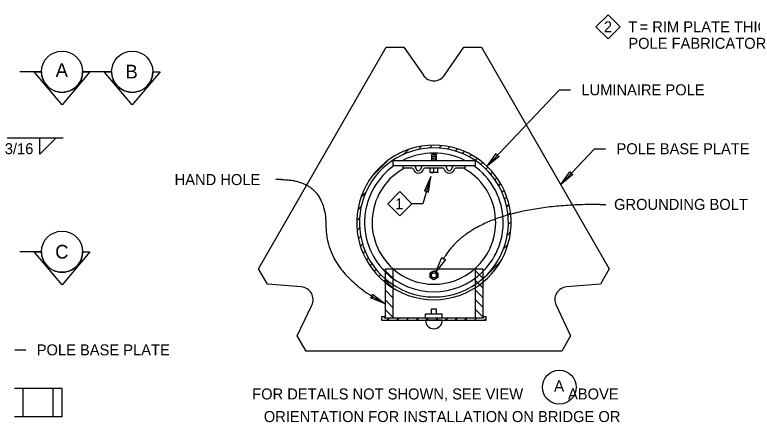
# Model space of a CAD drawing. Extents: x 99862 to 103151, y 100000 to 102076.
# Drawn here: x 100454 to 101528, y 100863 to 101456 of the extents above; entities that cross this region are included whole.
import ezdxf

# ---------------------------------------------------------------- set-up
doc = ezdxf.new("R2010")
doc.units = 0
for name, color, linetype in [('Level 15', 7, 'Continuous'), ('Level 20', 7, 'Continuous'), ('Level 21', 7, 'Continuous'), ('Level 3', 7, 'Continuous'), ('Level 62', 7, 'Continuous'), ('Level 7', 7, 'Continuous'), ('Level 8', 7, 'Continuous'), ('Level 9', 7, 'Continuous')]:
    doc.layers.add(name, color=color, linetype=linetype)

msp = doc.modelspace()

# ---------------------------------------------------------------- linework, layer by layer
at = {"layer": 'Level 15'}
for p, q in [((101247.4, 101347), (101142, 101235.6)), ((101247.4, 101347), (101263.4, 101347)), ((100425.2, 101277.3), (100524.4, 101277.3)), ((100490.5, 101253.3), (100490.5, 101277.3)), ((100490.5, 101253.3), (100514.5, 101277.3)), ((101298.6, 101261.2), (101249.3, 101209.2)), ((101298.6, 101261.2), (101314.6, 101261.2)), ((100842.1, 101216.3), (100834.1, 101216.3)), ((101060, 101220.9), (101048.6, 101181.2)), ((101048.6, 101181.2), (101032.6, 101181.2)), ((101307, 101180.2), (101315, 101180.2)), ((100454, 100968.4), (100470, 100968.4))]:
    msp.add_line(p, q, dxfattribs=at)
for points in [[(101142, 101235.6), (101155.5, 101254.2), (101156.9, 101251.4), (101159.8, 101250.1)], [(101249.3, 101209.2), (101262.8, 101227.8), (101264.3, 101225), (101267.2, 101223.7)], [(101060, 101220.9), (101050.8, 101199.8), (101054, 101200), (101056.6, 101198.2)], [(101067.4, 101081.8), (101076.3, 101103.1), (101078.3, 101100.7), (101081.4, 101100.1)], [(100993.4, 101035.4), (100972.1, 101044.3), (100974.5, 101046.3), (100975.1, 101049.4)]]:
    msp.add_lwpolyline(points, close=True, dxfattribs=at)
msp.add_open_spline([(101307, 101180.2), (101124.2, 101180.2), (101078.3, 101100.7)], degree=2, dxfattribs=at)
at = {"layer": 'Level 20'}
for points in [[(101318.2, 101456.3), (101335.8, 101438.7), (101318.2, 101421.2), (101300.7, 101438.7)], [(101015, 101198.8), (101032.6, 101181.2), (101015, 101163.7), (100997.4, 101181.2)]]:
    msp.add_lwpolyline(points, close=True, dxfattribs=at)
msp.add_open_spline([(100842.1, 101216.3), (100907.1, 101216.3), (100907.5, 101081.2), (100993.4, 101035.4)], degree=2, dxfattribs=at)
at = {"layer": 'Level 21'}
for p, q in [((101004.6, 101244.3), (101004.6, 101244.3)), ((101124.6, 101244.3), (101124.6, 101244.3)), ((100993.4, 101086.4), (100993.4, 101086.4))]:
    msp.add_line(p, q, dxfattribs=at)
at = {"layer": 'Level 3'}
for p, q in [((101041.5, 101259.8), (101046.7, 101265)), ((101058, 101262.1), (101062.2, 101266.3)), ((101072.1, 101262.1), (101075.8, 101265.8)), ((101020.5, 101252.9), (101027.8, 101260.2)), ((101084.6, 101260.4), (101088, 101263.9)), ((101096, 101257.7), (101099.2, 101260.9)), ((101106.4, 101254), (101109.4, 101257)), ((100974.2, 101220.8), (100997.6, 101244.2)), ((101116, 101249.4), (101118.9, 101252.4)), ((101124.8, 101244.1), (101127.7, 101247)), ((101132.9, 101238.1), (101135.8, 101241)), ((101140.4, 101231.4), (101143.3, 101234.3)), ((101147.2, 101224.1), (101150.1, 101227)), ((101153.4, 101216.1), (101156.3, 101219)), ((101158.9, 101207.4), (101161.8, 101210.4)), ((101163.6, 101198), (101166.7, 101201.1)), ((100958.4, 101190.8), (100965.6, 101198)), ((101167.6, 101187.9), (101170.7, 101191)), ((101170.6, 101176.7), (101173.9, 101180.1)), ((100953.6, 101171.9), (100958.7, 101177)), ((101172.5, 101164.5), (101176.2, 101168.2)), ((100952.2, 101156.4), (100956.4, 101160.6)), ((100952.7, 101142.7), (100956.5, 101146.4)), ((101173, 101150.9), (101177, 101154.9)), ((101171.3, 101135.1), (101176.2, 101140)), ((100954.7, 101130.5), (100958.1, 101133.9)), ((100957.7, 101119.4), (100960.9, 101122.6)), ((101166, 101115.6), (101172.5, 101122)), ((100961.5, 101109.1), (100964.6, 101112.2)), ((100966.2, 101099.6), (100969.1, 101102.6)), ((100971.5, 101090.8), (100974.4, 101093.7)), ((101135.9, 101071.3), (101161.6, 101097)), ((100977.6, 101082.7), (100980.4, 101085.5)), ((100993.4, 101086.4), (100993.4, 101015.2)), ((100993.4, 101086.4), (101004.6, 101086.4)), ((100993.4, 101083.9), (101004.6, 101072.6)), ((101004.6, 101086.4), (101004.6, 101015.2)), ((101004.6, 101086.4), (101124.6, 101086.4)), ((101124.6, 101086.4), (101124.6, 101015.2)), ((101124.6, 101086.4), (101135.9, 101086.4)), ((101124.6, 101084.1), (101135.9, 101072.9)), ((101135.9, 101086.4), (101135.9, 101015.2)), ((100984.2, 101075.2), (100987.1, 101078.1)), ((100991.5, 101068.4), (100993.4, 101070.2)), ((100993.4, 101069.7), (101004.6, 101058.5)), ((101124.6, 101070), (101135.9, 101058.7)), ((100993.4, 101055.6), (101004.6, 101044.3)), ((101124.6, 101055.8), (101135.9, 101044.6)), ((100993.4, 101041.4), (101004.6, 101030.2)), ((101124.6, 101041.7), (101135.9, 101030.4)), ((100988.7, 101011.4), (100988.7, 101017)), ((100988.7, 101017), (100992.4, 101017)), ((100992.4, 101015.2), (100992.4, 101017)), ((100993.4, 101027.3), (101004.6, 101016)), ((101124.6, 101027.6), (101135.9, 101016.3)), ((101136.8, 101015.2), (101136.8, 101017)), ((101136.8, 101017), (101140.6, 101017)), ((101140.6, 101017), (101140.6, 101017)), ((101140.6, 101011.4), (101140.6, 101017)), ((100988.7, 101011.4), (101140.6, 101011.4)), ((100992.4, 101015.2), (101136.8, 101015.2)), ((100996.2, 101011.4), (100999.9, 101015.2)), ((101004.6, 101015.2), (101124.6, 101015.2)), ((101010.3, 101011.4), (101014.1, 101015.2)), ((101024.5, 101011.4), (101028.2, 101015.2)), ((101038.6, 101011.4), (101042.4, 101015.2)), ((101052.8, 101011.4), (101056.5, 101015.2)), ((101066.9, 101011.4), (101070.7, 101015.2)), ((101081, 101011.4), (101084.8, 101015.2)), ((101095.2, 101011.4), (101098.9, 101015.2)), ((101109.3, 101011.4), (101113.1, 101015.2)), ((101123.5, 101011.4), (101127.2, 101015.2)), ((101137.6, 101011.4), (101140.6, 101014.4)), ((101140.6, 101011.4), (101140.6, 101011.4))]:
    msp.add_line(p, q, dxfattribs=at)
for radius, start, end in [(112.5, 309.2965, 230.7035), (108.5, 311.0634, 228.9366), (101, 63.5017, 116.4983), (101, 124.8487, 225.1147), (101, 314.8853, 55.1513), (101, 225.1147, 314.8853), (108.5, 228.9366, 311.0634), (112.5, 230.7035, 309.2965)]:
    msp.add_arc((101064.6, 101153.9), radius, start, end, dxfattribs=at)
at = {"layer": 'Level 62'}
for points in [[(101068.4, 101252.6), (101068.3, 101252.5), (101068.3, 101252.5), (101068.1, 101252.5), (101067, 101252.3), (101063.8, 101252.2), (101061.7, 101252.1), (101061.1, 101252), (101060.8, 101252), (101060.9, 101251.9)], [(101068.4, 101250.1), (101068.4, 101250), (101068.3, 101250), (101068.2, 101250), (101067.1, 101249.9), (101064, 101249.7), (101061.8, 101249.6), (101061.1, 101249.5), (101060.8, 101249.5), (101060.9, 101249.4)], [(101068.4, 101247.6), (101068.4, 101247.5), (101068.3, 101247.5), (101068.2, 101247.5), (101067.3, 101247.4), (101064.2, 101247.2), (101061.9, 101247.1), (101061.2, 101247), (101060.8, 101247), (101060.9, 101246.9)], [(101068.4, 101245.1), (101068.4, 101245), (101068.3, 101245), (101068.2, 101245), (101067.4, 101244.9), (101064.3, 101244.7), (101062, 101244.6), (101061.2, 101244.5), (101060.8, 101244.5), (101060.9, 101244.4)]]:
    msp.add_open_spline(points, degree=4, dxfattribs=at)
at = {"layer": 'Level 7'}
for p, q in [((100809.1, 101086.5), (100995.2, 101408.9)), ((100995.2, 101408.9), (101021, 101408.9)), ((101021, 101408.9), (101049.2, 101368.2)), ((101080, 101368.2), (101108.3, 101408.9)), ((101108.3, 101408.9), (101134, 101408.9)), ((101134, 101408.9), (101320.1, 101086.5)), ((100822, 101064.2), (100809.1, 101086.5)), ((101320.1, 101086.5), (101307.3, 101064.2)), ((100871.3, 101060.1), (100822, 101064.2)), ((101307.3, 101064.2), (101257.9, 101060.1)), ((100865.6, 100988.6), (100886.7, 101033.4)), ((101242.5, 101033.4), (101263.6, 100988.6)), ((100878.5, 100966.3), (100865.6, 100988.6)), ((101263.6, 100988.6), (101250.8, 100966.3)), ((101250.8, 100966.3), (100878.5, 100966.3))]:
    msp.add_line(p, q, dxfattribs=at)
for centre, radius, start, end in [((101064.6, 101378.9), 18.8, 214.7607, 325.2393), ((101064.6, 101153.9), 90, 118.4802, 228.5904), ((101064.6, 101153.9), 90, 311.4096, 61.5198), ((101064.6, 101153.9), 90, 228.5904, 311.4096), ((100869.8, 101041.4), 18.8, 334.7607, 85.2393), ((101259.5, 101041.4), 18.8, 94.7607, 205.2393)]:
    msp.add_arc(centre, radius, start, end, dxfattribs=at)
at = {"layer": 'Level 8'}
for p, q in [((101004.6, 101244.3), (101124.6, 101244.3)), ((101004.6, 101244.3), (101004.6, 101236.8)), ((101124.6, 101244.3), (101124.6, 101236.8)), ((101004.6, 101236.8), (101019.6, 101236.8)), ((101019.6, 101236.8), (101109.6, 101236.8)), ((101019.6, 101233), (101019.6, 101236.8)), ((101019.6, 101236.8), (101034.6, 101236.8)), ((101032.9, 101233), (101019.6, 101233)), ((101077.9, 101233), (101051.3, 101233)), ((101094.6, 101236.8), (101109.6, 101236.8)), ((101109.6, 101233), (101096.3, 101233)), ((101109.6, 101236.8), (101124.6, 101236.8)), ((101109.6, 101236.8), (101109.6, 101233)), ((100522.9, 100912.1), (100453.5, 100912.1)), ((100466.4, 100870.8), (100466.4, 100912.1)), ((100510, 100870.8), (100510, 100912.1)), ((100522.9, 100870.8), (100522.9, 100912.1)), ((100522.9, 100870.8), (100453.5, 100870.8))]:
    msp.add_line(p, q, dxfattribs=at)
for centre, radius, start, end in [((101032.9, 101231.1), 1.88, 11.537, 90), ((101034.6, 101233), 3.75, 360, 90), ((101042.1, 101233), 3.75, 180, 0), ((101049.6, 101233), 3.75, 90, 180), ((101051.3, 101231.1), 1.88, 90, 168.463), ((101077.9, 101231.1), 1.88, 11.537, 90), ((101079.6, 101233), 3.75, 360, 90), ((101087.1, 101233), 3.75, 180, 0), ((101094.6, 101233), 3.75, 90, 180), ((101096.3, 101231.1), 1.88, 90, 168.463), ((101042.1, 101233), 7.5, 191.537, 348.463), ((101087.1, 101233), 7.5, 191.537, 348.463)]:
    msp.add_arc(centre, radius, start, end, dxfattribs=at)
at = {"layer": 'Level 9'}
for p, q in [((100492.9, 101373.3), (100461.3, 101373.3)), ((100482.3, 101373.3), (100492.9, 101373.3)), ((100522.9, 101324.9), (100482.3, 101373.3)), ((100563.5, 101373.3), (100522.9, 101324.9)), ((100552.9, 101373.3), (100563.5, 101373.3)), ((100595.1, 101373.3), (100552.9, 101373.3)), ((100584.5, 101373.3), (100595.1, 101373.3)), ((100625.1, 101324.9), (100584.5, 101373.3)), ((100665.7, 101373.3), (100625.1, 101324.9)), ((100655.1, 101373.3), (100665.7, 101373.3)), ((101061.5, 101253), (101060.9, 101252.3)), ((101068.4, 101252.3), (101060.9, 101252.3)), ((101060.9, 101252.3), (101060.9, 101244.3)), ((101067.7, 101253), (101061.5, 101253)), ((101068.4, 101252.3), (101067.7, 101253)), ((101068.4, 101244.3), (101068.4, 101252.3)), ((101059, 101227), (101059, 101233)), ((101064.6, 101227), (101064.6, 101233)), ((101070.2, 101227), (101070.2, 101233)), ((101067.4, 101226.5), (101059, 101226.5)), ((101070.2, 101226.5), (101067.4, 101226.5)), ((100491.3, 101111.3), (100461.3, 101111.3)), ((100482.3, 101111.3), (100492.9, 101111.3)), ((100522.9, 101062.9), (100482.3, 101111.3)), ((100563.5, 101111.3), (100522.9, 101062.9)), ((100552.9, 101111.3), (100563.5, 101111.3)), ((101059, 101076.9), (101059, 101077)), ((101061.9, 101072), (101061.7, 101072.1)), ((101067.6, 101072.1), (101067.3, 101072)), ((101070.2, 101077), (101070.2, 101076.8)), ((101060.9, 101020.8), (101060.9, 101028.3)), ((101060.9, 101028.3), (101068.4, 101028.3)), ((101068.4, 101020.8), (101068.4, 101028.3)), ((101052.4, 101015.2), (101052.4, 101020.8)), ((101052.4, 101020.8), (101076.8, 101020.8)), ((101076.8, 101015.2), (101076.8, 101020.8)), ((101076.8, 101011.4), (101052.4, 101011.4))]:
    msp.add_line(p, q, dxfattribs=at)
for centre, radius in [((100522.9, 101373.3), 30), ((100625.1, 101373.3), 30), ((100522.9, 101111.3), 30), ((101064.6, 101076.9), 3.75), ((101247.3, 100914), 24.7)]:
    msp.add_circle(centre, radius, dxfattribs=at)
for centre, radius, start, end in [((100522.9, 101373.3), 30, 179.9978, 0.0022), ((100625.1, 101373.3), 30, 179.9978, 0.0022), ((100522.9, 101111.3), 30, 179.9978, 0.0022), ((101064.6, 101076.9), 5.63, 60, 179.2446), ((101064.6, 101076.9), 5.63, 1.1969, 60), ((101064.6, 101076.9), 5.63, 180.758, 238.5832), ((101064.6, 101076.9), 5.63, 241.4168, 298.4392), ((101064.6, 101076.9), 5.63, 301.5608, 358.8031), ((101064.6, 101011.4), 12.2, 180, 0)]:
    msp.add_arc(centre, radius, start, end, dxfattribs=at)
for points, degree in [([(101059, 101226.5), (101059, 101226.5), (101059, 101226.5), (101059, 101226.7), (101059, 101226.8), (101059, 101227)], 3), ([(101059, 101227), (101059.9, 101226.7), (101060.8, 101226.5), (101062.3, 101226.5), (101062.8, 101226.5), (101063.7, 101226.7), (101064.2, 101226.8), (101064.6, 101227)], 3), ([(101067.4, 101226.5), (101067, 101226.5), (101066.5, 101226.5), (101065.5, 101226.7), (101065.1, 101226.8), (101064.6, 101227)], 3), ([(101070.2, 101227), (101069.8, 101226.8), (101069.3, 101226.7), (101068.4, 101226.5), (101067.9, 101226.5), (101067.4, 101226.5)], 3), ([(101070.2, 101227), (101070.2, 101226.7), (101070.2, 101226.5), (101070.2, 101226.5)], 2), ([(101059, 101080.2), (101059.9, 101080.7), (101060.8, 101081.2), (101062.3, 101082.1), (101062.8, 101082.3), (101063.7, 101082.9), (101064.2, 101083.2), (101064.6, 101083.4)], 3), ([(101067.4, 101081.8), (101067, 101082.1), (101066.5, 101082.3), (101065.5, 101082.9), (101065.1, 101083.2), (101064.6, 101083.4)], 3), ([(101070.2, 101080.2), (101069.8, 101080.4), (101069.3, 101080.7), (101068.4, 101081.2), (101067.9, 101081.5), (101067.4, 101081.8)], 3), ([(101059, 101077), (101059, 101077.5), (101059, 101078.1), (101059, 101079.1), (101059, 101079.7), (101059, 101080.2)], 3), ([(101059, 101073.7), (101059, 101074.7), (101059, 101075.8), (101059, 101076.9)], 2), ([(101061.7, 101072.1), (101061.2, 101072.4), (101060.8, 101072.7), (101059.9, 101073.2), (101059.4, 101073.4), (101059, 101073.7)], 3), ([(101064.6, 101070.4), (101064.2, 101070.7), (101063.7, 101070.9), (101062.8, 101071.5), (101062.4, 101071.7), (101061.9, 101072)], 3), ([(101067.3, 101072), (101066.4, 101071.5), (101065.5, 101070.9), (101064.6, 101070.4)], 2), ([(101070.2, 101073.7), (101069.4, 101073.2), (101068.5, 101072.7), (101067.6, 101072.1)], 2), ([(101070.2, 101080.2), (101070.2, 101079.1), (101070.2, 101078.1), (101070.2, 101077)], 2), ([(101070.2, 101076.8), (101070.2, 101076.3), (101070.2, 101075.7), (101070.2, 101074.7), (101070.2, 101074.2), (101070.2, 101073.7)], 3)]:
    msp.add_open_spline(points, degree=degree, dxfattribs=at)

# ---------------------------------------------------------------- texts
at = {"layer": 'Level 15'}
msp.add_text('3/16', height=16, dxfattribs=at).set_placement((100439.5, 101253.3))
at = {"layer": 'Level 20'}
for s, height, p in [('2', 16, (101312.2, 101430.7)), ('T', 16, (101347.8, 101430.7)), (' = RIM PLATE THICKNESS BY LUMINAIRE ', 16, (101358.3, 101430.7)), ('POLE FABRICATOR', 16, (101347.8, 101406.7)), ('A', 20, (100513.6, 101365.7)), ('B', 20, (100615.4, 101363.5)), ('LUMINAIRE POLE', 16, (101279.4, 101339)), ('POLE BASE PLATE', 16, (101330.6, 101253.2)), ('HAND HOLE', 16, (100686.9, 101208.3)), ('1', 16, (101008.1, 101173.2)), ('GROUNDING BOLT', 16, (101327, 101172.2)), ('C', 20, (100513, 101101.3)), ('A', 16.5, (101239.6, 100907.7)), ('FOR DETAILS NOT SHOWN, SEE VIEW           ABOVE', 16, (100799.9, 100896.2)), ('ORIENTATION FOR INSTALLATION ON BRIDGE OR ', 16, (100816.8, 100863.3))]:
    msp.add_text(s, height=height, dxfattribs=at).set_placement(p)
msp.add_text('POLE BASE PLATE', height=16, rotation=360, dxfattribs=at).set_placement((100486, 100960.4))

doc.saveas('drawing.dxf')
